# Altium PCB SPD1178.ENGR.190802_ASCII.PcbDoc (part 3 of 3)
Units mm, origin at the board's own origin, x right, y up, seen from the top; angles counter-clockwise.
Board outline 150 x 150 mm, 2 copper layers (Top Layer, Bottom Layer); 315 components, 164 nets, 838 pads, 882 vias.
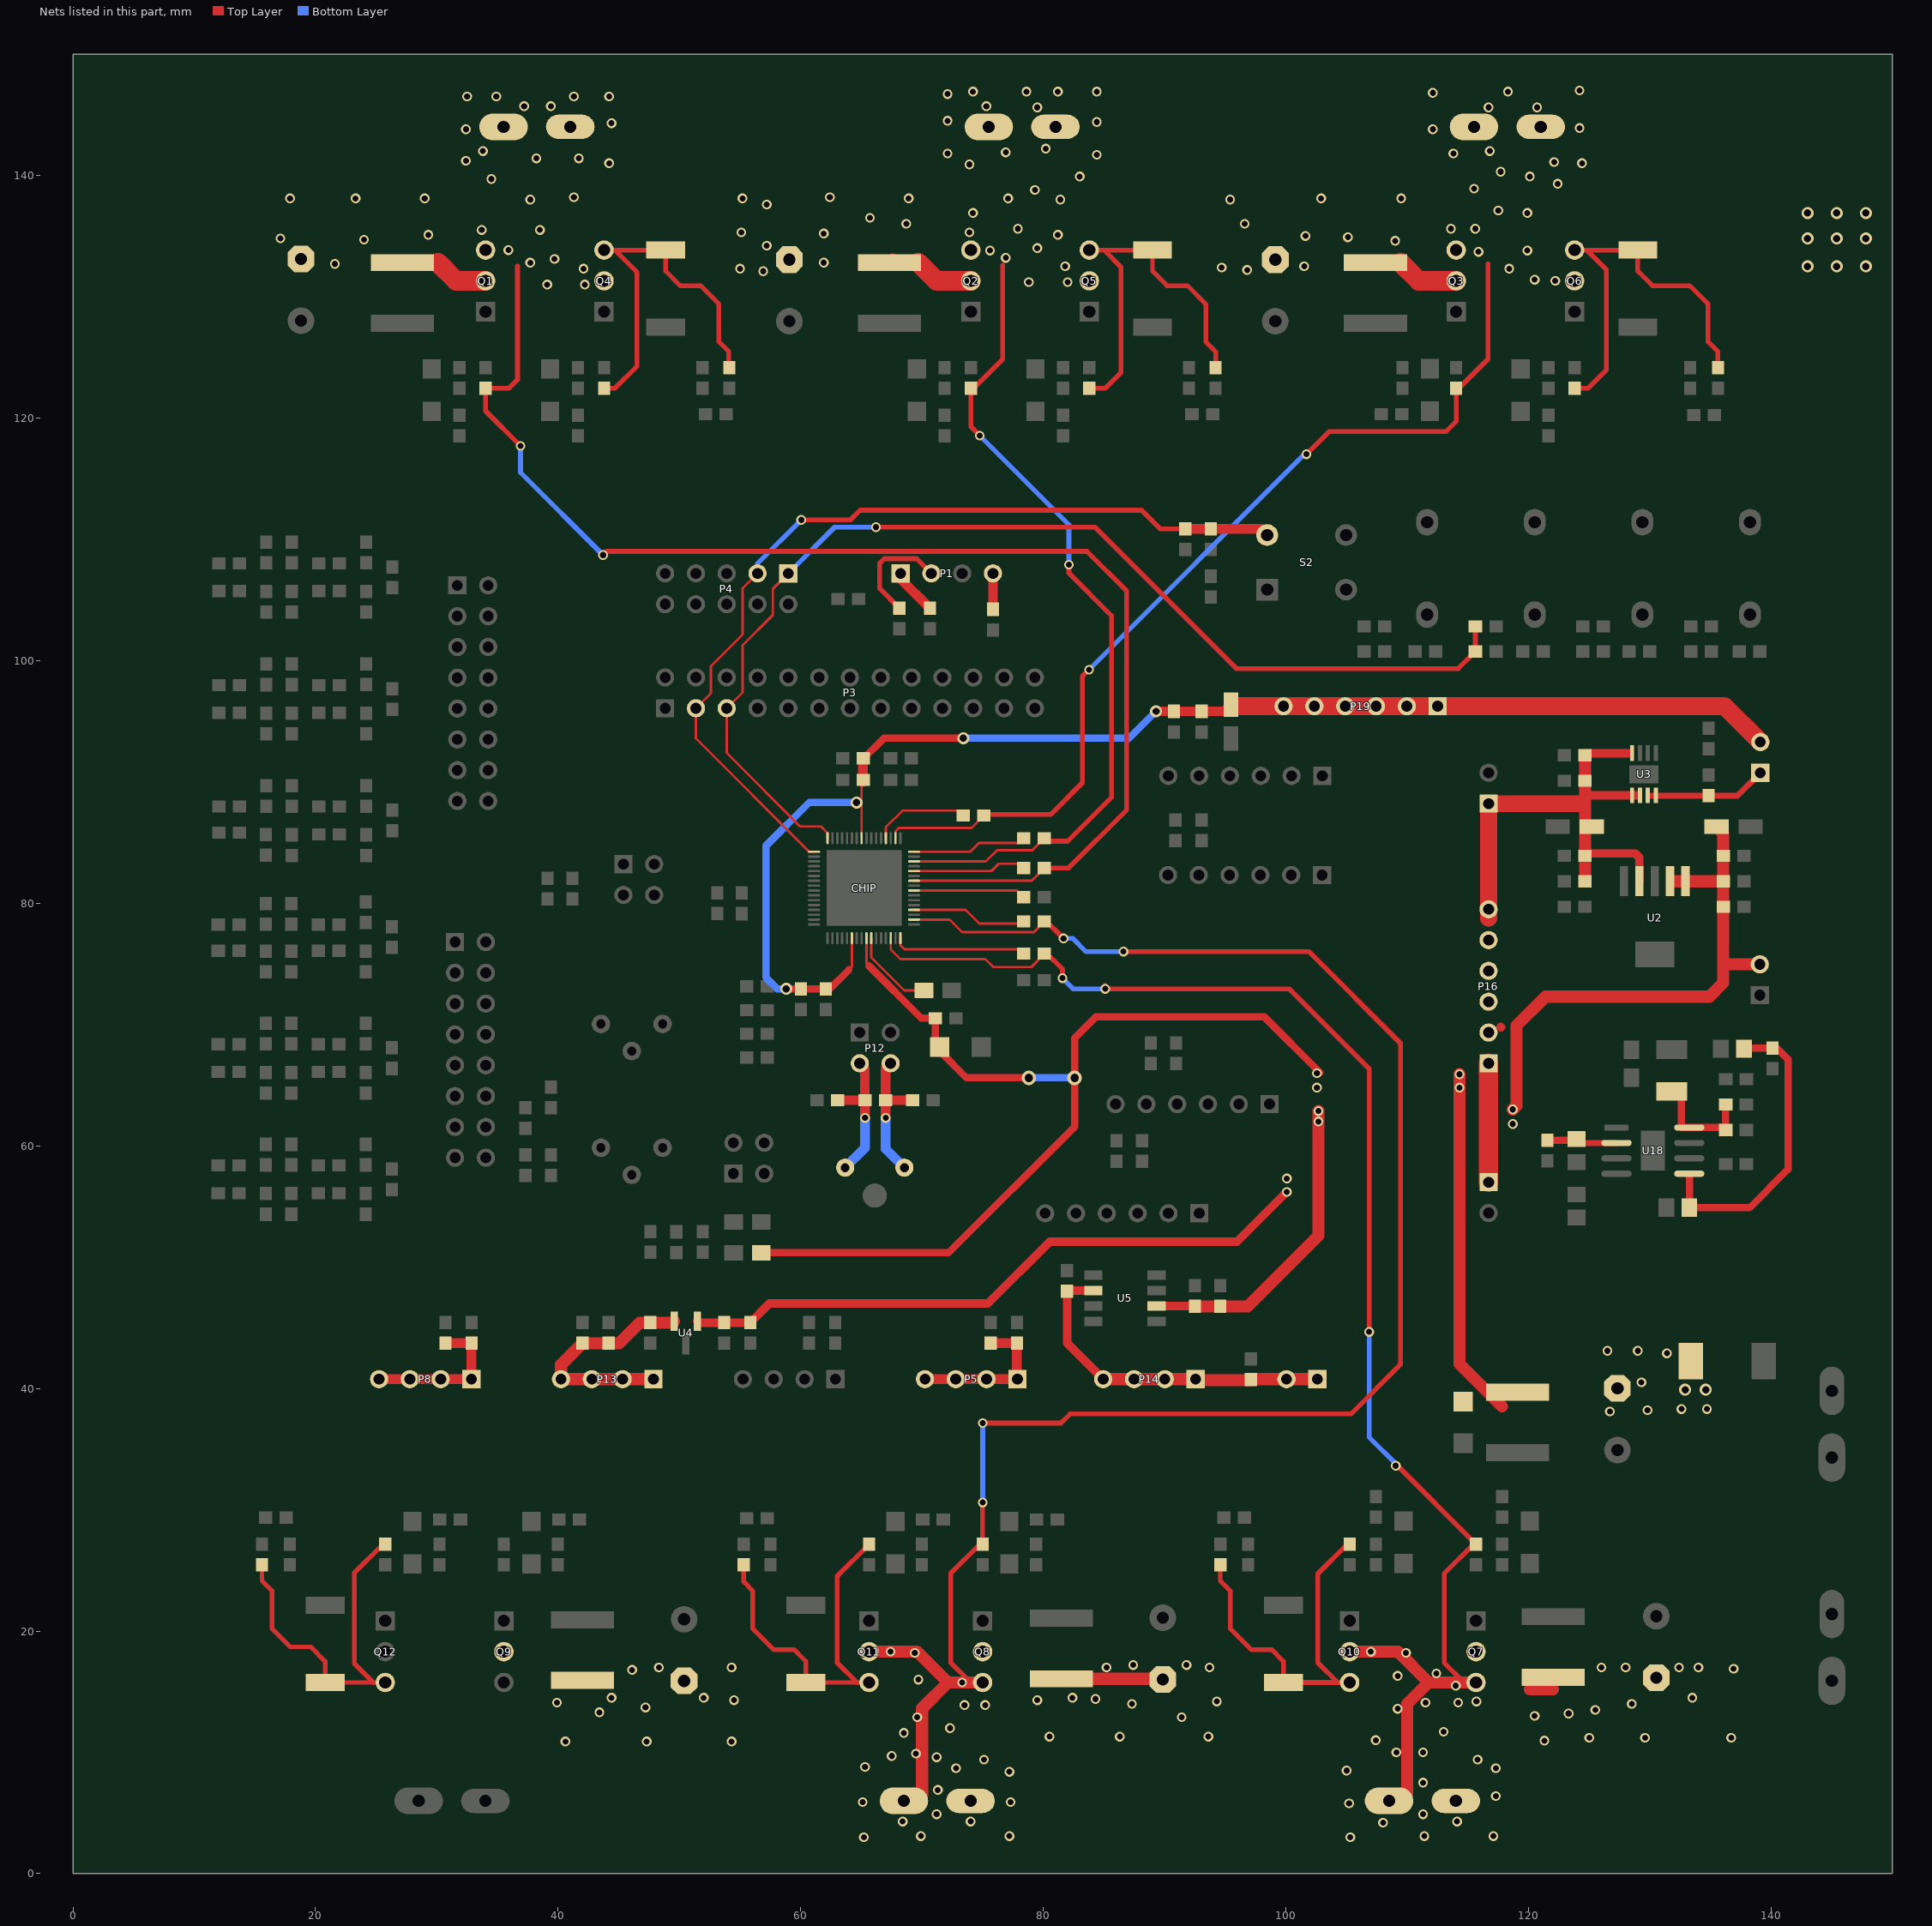
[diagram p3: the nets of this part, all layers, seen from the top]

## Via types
v1: diameter 0.8, hole 0.5, Top Layer to Bottom Layer, tented both sides, 575 vias
v2: diameter 1, hole 0.6, Top Layer to Bottom Layer, 157 vias
v3: diameter 0.8, hole 0.5, Top Layer to Bottom Layer, 69 vias
v4: diameter 1, hole 0.6, Top Layer to Bottom Layer, tented both sides, 52 vias
v5: diameter 0.8, hole 0.4, Top Layer to Bottom Layer, 16 vias
v6: diameter 1.2, hole 0.7, Top Layer to Bottom Layer, tented both sides, 7 vias
v7: diameter 0.5, hole 0.3, Top Layer to Bottom Layer, 6 vias

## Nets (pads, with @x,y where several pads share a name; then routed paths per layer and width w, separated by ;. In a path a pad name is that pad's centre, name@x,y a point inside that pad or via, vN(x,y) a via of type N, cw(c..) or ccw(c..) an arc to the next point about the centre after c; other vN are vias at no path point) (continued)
PX0_V: C14.2 C79.2 CHIP.34 Q8.3 Q11.2 V2.1 | length 151.7
  Top Layer w0.2: CHIP.34@69.333,78.647 72.283,78.647 73.31,77.62 79.22,77.62 C14.2@80.18,78.58
  Top Layer w0.4: 74.003,15.764 72.367,17.4 72.367,24.767 C79.2@74.755,27.155 ; C79.2@74.994,27.155 74.994,30.594 v1(75,30.6) ; v1(75,37.146) 81.446,37.146 82.2,37.9 105.353,37.9 109.446,41.993 109.446,68.444 101.875,76.015 v1(86.6,76.015) ; C14.2@80.18,78.58 v1(81.66,77.1)
  Top Layer w1: Q11.2@65.626,18.304 v1(67.4,18.304) 69.602,18.304 72.142,15.764 ; V2.1@70,6.5 70,13.622 72.142,15.764 ; Q8.3@74.994,15.764 74.003,15.764 v1(73.3,15.764) 72.142,15.764
  Bottom Layer w0.4: v1(75,30.6) v1(75,37.146) ; v1(81.66,77.1) 82.41,77.1 83.495,76.015 v1(86.6,76.015)
  other v1: 65.2,3 69.9,3.1 77.2,3.1 68.4,4.3 74,4.3 71.2,4.9 65.1,5.9 77.3,5.9 71.3,6.9 77.2,8.4 72.8,8.7 65.3,8.8 75.1,9.4 71.2,9.6 67.5,9.7 69.5,9.9 68.5,11.6 72.3,12 69.6,12.9 73.5,13.9 75.2,13.9 69.7,16 69.4,18.2
PX0_W: C15.2 C77.2 CHIP.30 Q7.3 Q10.2 W2.1 | length 123.7
  Top Layer w0.2: CHIP.30@67.413,77.117 67.413,76.203 68.216,75.4 75.215,75.4 75.877,74.738 79.008,74.738 C15.2@80.065,75.795
  Top Layer w0.4: C15.2@80.065,75.845 80.065,75.795 80.345,75.795 81.57,74.57 v1(81.57,73.82) ; v1(85.1,72.936) 100.274,72.936 106.855,66.355 v1(106.855,44.662) ; v1(109.05,33.63) 109.05,33.769 C77.2@115.664,27.155 115.455,27.155 113.037,24.737 113.037,17.4 114.673,15.764
  Top Layer w1: Q10.2@105.25,18.304 109.226,18.304 111.766,15.764 ; W2.1@110,6.5 110,13.998 111.766,15.764 ; Q7.3@115.664,15.764 114.673,15.764 111.766,15.764
  Bottom Layer w0.4: v1(81.57,73.82) 82.454,72.936 v1(85.1,72.936) ; v1(106.855,44.662) 106.855,35.975 109.05,33.78 v1(109.05,33.63)
  other v1: 105.3,3 111.4,3.1 117.1,3.1 108,4.2 114.1,4.3 111.3,4.9 105.2,5.8 117.3,6.4 111.3,7.5 105,8.5 117.3,8.7 115.8,9.4 109.1,10 111.3,10 107.4,11 113,11.7 109.2,13.6 111.5,14.1 114.2,14.1 115.7,14.2 114,15.5 109.2,16.3 112.4,16.5 109.9,18.2 107,18.3
PX1_U: C22.2 C75.2 CHIP.50 Q3.3 Q6.2 U1.1 | length 80.1
  Top Layer w0.2: CHIP.50@67.813,85.367 67.813,85.933 68.08,86.2 74.08,86.2 C22.2@75.1,87.22
  Top Layer w0.4: C22.2@75.1,87.22 75.2,87.32 80.61,87.32 83.22,89.93 83.22,98.71 v1(83.76,99.25) ; v3@101.493,116.98 v3@101.601,117.089 ; v3(101.68,117.01) 103.54,118.87 113.18,118.87 114.029,119.719 C75.2@114.029,122.451 114.251,122.451 116.656,124.856 116.656,132.7
  Top Layer w1: Q3.3@114.003,133.842 Q3.3@114.019,133.842
  Bottom Layer w0.4: v1(83.76,99.25) 83.763,99.25 v3@101.493,116.98
  other v1: 122.2,131.302 120.5,131.4 118.4,132.3 115.869,133.7 119.9,133.8 113.6,135.6 115.6,135.6 119.9,136.9 117.5,137.1 115.5,138.9 122.4,139.3 120.1,139.9 117.7,140.3 124.4,141 122.1,141.1 113.8,141.8 116.8,142 112.1,143.8 124.2,143.9 116.7,145.6 120.7,145.6 112.1,146.8 118.3,146.9 124.2,147
PX1_V: C23.2 C74.2 CHIP.46 Q2.3 Q5.2 V1.1 | length 68.6
  Top Layer w0.2: CHIP.46@69.333,83.447 75.257,83.447 76.18,84.37 79.08,84.37 C23.2@80.07,85.36
  Top Layer w0.4: v1(74.75,118.55) 74.024,119.276 C74.2@74.024,122.451 74.251,122.451 76.651,124.851 76.651,132.6 ; C23.2@80.07,85.36 80.32,85.11 82,85.11 85.61,88.72 85.61,103.71 82.1,107.22 v1(82.1,107.91)
  Top Layer w1: Q2.3@74.008,133.842 Q2.3@74.024,133.842
  Bottom Layer w0.4: v1(74.75,118.55) 82.1,111.2 v1(82.1,107.91)
  other v1: 78.8,131.2 82,131.2 81.8,132.5 76.9,133.2 75.6,133.8 79.5,134 81.2,135.1 73.9,135.3 77.9,135.6 74.2,136.9 81.4,138 77.1,138.1 79.3,138.8 83,139.9 73.9,140.9 84.4,141.7 72.1,141.8 76.9,141.9 80.2,142.2 84.4,144.4 72.1,144.5 79.5,145.6 75.3,145.7 72.1,146.7 74.2,146.9 78.6,146.9 81.2,146.9 84.4,146.9
PX1_W: C24.2 C71.2 CHIP.42 Q1.3 Q4.2 W1.1 | length 112.7
  Top Layer w0.2: CHIP.42@69.333,81.847 79.047,81.847 80.065,82.865 C24.2@80.065,82.9
  Top Layer w0.4: 36.646,132.5 36.646,123.156 35.941,122.451 C71.2@34.019,122.451 34.019,120.581 v1(36.9,117.7) ; v1(43.7,108.7) 44,109 83.6,109 86.87,105.73 86.87,87.69 82.08,82.9 C24.2@80.07,82.9
  Top Layer w1: Q1.3@34.013,133.842 Q1.3@34.019,133.842 Q1.3@34.029,133.842
  Bottom Layer w0.4: v1(36.9,117.7) 36.9,115.5 v1(43.7,108.7)
  other v1: 39.1,131 42.2,131 42.1,132.3 37.7,132.8 39.7,133.1 35.9,133.842 33.7,135.5 38.5,135.5 37.7,138 41.3,138.2 34.5,139.7 44.2,141 32.4,141.2 38.2,141.4 41.7,141.4 33.8,142 32.4,143.8 44.4,144.3 37.2,145.7 39.4,145.7 32.5,146.5 34.9,146.5 41.3,146.5 44.2,146.5
RU0: C82.2 Q12.3 R30.2 R185.1 | length 31
  Top Layer w0.381: R185.1@15.588,25.455 15.588,24.146 16.404,23.33 16.404,20.209 17.913,18.7 19.6,18.7 20.795,17.505 R30.2@20.795,15.764 24.757,15.764 Q12.3@25.748,15.764
  Top Layer w0.4: 24.757,15.764 23.2,17.321 23.2,24.8 25.555,27.155 C82.2@25.748,27.155
RU1: C76.2 Q6.3 R15.2 R155.1 | length 33.2
  Top Layer w0.381: Q6.3@123.792,133.842 R15.2@128.999,133.842 128.999,132.101 130.194,130.906 133.281,130.906 134.79,129.397 134.79,126.276 135.606,125.46 R155.1@135.606,124.151
  Top Layer w0.4: C76.2@123.792,122.451 124.9,122.451 126.419,123.97 126.419,132.206 124.783,133.842
RV0: C80.2 Q11.3 R29.2 R175.1 | length 31.2
  Top Layer w0.381: R175.1@55.3,25.45 55.3,24.058 56.028,23.33 56.028,20.209 57.761,18.476 59.448,18.476 60.419,17.505 R29.2@60.419,15.764 64.635,15.764 Q11.3@65.626,15.764
  Top Layer w0.4: 64.635,15.764 62.999,17.4 62.999,24.528 C80.2@65.626,27.155
RV1: C73.2 Q5.3 R14.2 R145.1 | length 31.9
  Top Layer w0.381: R14.2@88.994,133.842 88.994,132.101 90.189,130.906 91.876,130.906 93.385,129.397 93.385,126.276 94.201,125.46 R145.1@94.2,124.15
  Top Layer w0.4: C73.2@83.787,122.451 85.1,122.451 86.4,123.751 86.4,132.437 84.995,133.842 ; Q5.3@83.787,133.842 84.995,133.842 ; R14.2@88.994,133.842 84.995,133.842
RW0: C78.2 Q10.3 R28.2 R165.1 | length 31.6
  Top Layer w0.381: R165.1@94.582,25.455 94.582,24.146 95.398,23.33 95.398,20.209 97.131,18.476 98.818,18.476 99.789,17.505 R28.2@99.789,15.764
  Top Layer w0.4: R28.2@99.789,15.764 104.259,15.764 ; Q10.3@105.25,15.764 104.259,15.764 ; C78.2@105.25,27.155 105.055,27.155 102.623,24.723 102.623,17.4 104.259,15.764
RW1: C72.2 Q4.3 R13.2 R135.1 | length 31.7
  Top Layer w0.381: R13.2@48.862,133.842 48.862,132.101 50.057,130.906 51.744,130.906 53.253,129.397 53.253,126.276 54.069,125.46 R135.1@54.069,124.151
  Top Layer w0.4: C72.2@43.782,122.451 44.682,122.451 46.5,124.269 46.5,132.013 44.671,133.842 ; Q4.3@43.782,133.842 44.671,133.842 ; R13.2@48.862,133.842 44.671,133.842
TRSTN: CHIP.64 CL8.1 P3.5 P4.1 R31.1 | length 94.2
  Top Layer w0.2: P4.1@58.978,107.188 57.7,105.91 57.7,103.75 55.2,101.25 55.2,97.371 P3.5@53.898,96.069 53.898,92.382 59.95,86.33 61.67,86.33 62.213,85.787 CHIP.64@62.213,85.367
  Top Layer w0.4: v1(66.2,111) 84.251,111 95.911,99.34 114.2,99.34 R31.1@115.61,100.75 CL8.1@115.61,102.81
  Bottom Layer w0.4: P4.1@58.978,107.188 62.79,111 v1(66.2,111) v1@66.2,110.9
UART_RXD: P1.2 R64.2 | length 9.3
  Top Layer w0.4: R64.2@68.13,104.32 66.51,105.94 66.51,108.03 66.88,108.4 69.553,108.4 P1.2@70.765,107.188
UART_TXD: P1.1 R75.2 | length 3.4
  Top Layer w0.8: P1.1@68.225,106.745 R75.2@70.65,104.32
VBAT: C1.1 C2.1 C3.1 C4.1 C5.1 C6.1 C16.1 C17.1 C18.1 C19.1 C20.1 C21.1 C28.1 C29.1 C30.1 CHIP.25 CL32.2 CL33.2 F1.2 Q1.2 Q2.2 Q3.2 Q7.2 Q8.2 Q9.2 R57.1 R58.1 R440.2 U18.2 | length 155.1
  Top Layer w0.2: 65.413,75.047 CHIP.25@65.413,77.117
  Top Layer w0.5: R58.1@124.276,60.24 U18.2@127.244,60.24
  Top Layer w0.6: C18.1@50.346,15.931 C18.1@50.386,15.891 ; R440.2@56.752,51.181 72.181,51.181 82.58,61.58 82.58,68.88 84.34,70.64 98.2,70.64 v1@102.79,66.05 ; 65.62,74.84 69.94,70.52 CL33.2@71.08,70.52 71.08,68.506 CL32.2@71.446,68.14 71.446,67.814 73.66,65.6 v6(78.8,65.6) ; R57.1@121.548,60.455 123.861,60.455 R58.1@123.961,60.555 R58.1@124.276,60.24
  Top Layer w1: C21.1@40.935,15.931 C21.1@42.004,15.931 ; C20.1@79.442,16.058 C20.1@81.471,16.058 89.813,16.058 C17.1@89.853,16.018 ; v1(114.3,65.9) v1(114.3,64.8) 114.3,42.014 117.8,38.515 ; 120.115,15.185 122.014,15.185
  Top Layer w1.016: C4.1@27.17,132.807 30.093,132.807 ; C5.1@67.323,132.807 C5.1@67.815,132.807 ; C5.1@67.569,133.053 C5.1@67.815,132.807 ; C5.1@69.693,132.807 C5.1@67.815,132.807 ; C6.1@107.374,132.807 C6.1@109.443,132.807
  Top Layer w1.6: 30.093,132.807 31.598,131.302 Q1.2@34.019,131.302 ; C5.1@69.693,132.807 71.198,131.302 Q2.2@74.024,131.302 ; C6.1@109.443,132.807 110.948,131.302 Q3.2@114.029,131.302
  Bottom Layer w0.6: v6(78.8,65.6) v6(82.58,65.6)
  other v1: 40.6,10.9 47.3,10.9 54.3,10.9 121.3,10.967 125,11.2 129.6,11.2 136.7,11.2 80.5,11.3 86.3,11.3 93.6,11.3 91.4,12.9 120.5,13 123.3,13.2 43.4,13.3 125.5,13.5 47.2,13.7 87.3,14 128.5,14 39.9,14.1 94.3,14.2 54.5,14.3 79.5,14.3 84.3,14.4 44.4,14.5 52,14.5 82.4,14.5 133.5,14.5 46.1,16.8 136.9,16.9 48.3,17 54.3,17 85.2,17 93.7,17 126,17 128,17 132.4,17 134,17 87.4,17.2 91.8,17.2 126.7,38.1 129.8,38.2 132.6,38.3 134.7,38.3 129.3,40.5 131.4,42.9 126.5,43.1 129,43.1 102.55,64.8 102.55,65.99 56.9,132.1 96.8,132.2 55,132.3 94.7,132.4 101.5,132.5 21.6,132.7 61.9,132.807 57.2,134.2 109,134.6 24,134.7 17.1,134.8 105.1,134.9 101.6,135 29.3,135.1 61.9,135.2 55.1,135.3 68.7,136 96.6,136 65.7,136.5 57.2,137.6 95.4,138 17.9,138.1 23.3,138.1 29,138.1 55.2,138.1 68.9,138.1 102.9,138.1 109.5,138.1 62.4,138.2
  other v2: 132.9,39.9 134.6,39.9
  other v4: 143,132.5 145.4,132.5 147.8,132.5 143,134.8 145.4,134.8 147.8,134.8 143,136.9 145.4,136.9 147.8,136.9
VBOOT0_U: C13.1 CHIP.40 | length 9.3
  Top Layer w0.2: CHIP.40@69.333,81.047 77.823,81.047 C13.1@78.37,80.5
VBOOT0_V: C14.1 CHIP.36 | length 9.7
  Top Layer w0.2: CHIP.36@69.333,79.447 73.593,79.447 74.72,78.32 78.01,78.32 C14.1@78.37,78.68
VBOOT0_W: C15.1 CHIP.32 | length 11.1
  Top Layer w0.2: CHIP.32@68.213,77.117 68.213,76.534 68.547,76.2 78.238,76.2 78.238,75.972 C15.1@78.36,75.85
VBOOT1_U: C22.1 CHIP.52 | length 8
  Top Layer w0.2: CHIP.52@67.013,85.367 67.013,86.264 68.379,87.63 72.99,87.63 C22.1@73.4,87.22
VBOOT1_V: C23.1 CHIP.48 | length 9.5
  Top Layer w0.2: CHIP.48@69.333,84.247 73.987,84.247 74.7,84.96 77.97,84.96 C23.1@78.37,85.36
VBOOT1_W: C24.1 CHIP.44 | length 9.4
  Top Layer w0.2: CHIP.44@69.333,82.647 75.727,82.647 76.33,83.25 78.02,83.25 C24.1@78.37,82.9
VCAP12: CB3.1 CHIP.22 CHIP.57 CL11.2 CL12.2 CL25.1 CL26.1 CL30.2 CL31.2 P18.2 P19.1 P19.2 P19.3 P19.4 P19.5 P19.6 | length 113.8
  Top Layer w0.2: 63.97,74.51 64.213,74.753 CHIP.22@64.213,77.117 ; CHIP.57@65.013,85.367 CL31.2@65.013,90
  Top Layer w0.6: v2(58.81,72.94) CL12.2@60.02,72.94 62.4,72.94 63.97,74.51 ; CL30.2@65.15,91.9 66.85,93.6 v2(73.4,93.6)
  Top Layer w0.8: CL31.2@65.11,90 CL30.2@65.11,92.02 ; v2(89.29,95.818) CL25.1@90.756,95.818 CL26.1@93.042,95.818 94.905,95.818 CB3.1@95.455,96.368
  Top Layer w1.5: CB3.1@95.75,96.24 136.155,96.24 P18.2@139.105,93.29
  Bottom Layer w0.6: v2(58.81,72.94) 58.06,72.94 57.13,73.87 57.13,84.74 60.69,88.3 v2(64.6,88.3) ; v2(73.4,93.6) 87.032,93.6 87.052,93.58 v2(89.29,95.818)
VCC: P1.4 R62.1 | length 3
  Top Layer w0.8: R62.1@75.845,104.228 P1.4@75.845,107.188
VDAC_BUF0: CL4.1 P5.1 P5.2 P5.3 P5.4 R169.1 | length 12.8
  Top Layer w0.8: P5.4@70.237,40.767 P5.3@72.777,40.767 P5.2@75.317,40.767 P5.1@77.857,40.767 77.818,40.806 CL4.1@77.818,43.727 R169.1@75.659,43.727
VDAC_BUF1: CL5.1 P8.1 P8.2 P8.3 P8.4 R168.1 | length 12.7
  Top Layer w0.8: P8.4@25.237,40.767 P8.3@27.777,40.767 P8.2@30.317,40.767 P8.1@32.857,40.767 32.86,40.77 R168.1@32.86,43.727 CL5.1@30.701,43.727
VDD_1V3: CL24.1 P18.1 U3.3 U3.4 | length 10
  Top Layer w0.5: U3.3@129.92,88.86 CL24.1@134.85,88.86 137.215,88.86 P18.1@139.105,90.75
VDD_3V3: CB1.1 CB6.1 CB8.2 CF2.1 CL22.1 CL23.1 CL29.2 P16.1 P16.2 P16.3 P16.4 P16.5 P16.6 P27.1 P28.1 U2.4 U3.1 U3.2 U3.8 U4.1 | length 105.8
  Top Layer w0.7: U4.1@51.473,45.537 51.583,45.427 CL29.2@53.688,45.427 CB8.2@55.847,45.427 57.42,47 75.43,47 80.53,52.1 95.97,52.1 v1(100.07,56.2) ; 117.7,69.8 117.724,69.776 ; CL22.1@124.65,83.9 124.85,84.1 128.8,84.1 129.13,83.77 U2.4@129.13,81.825 ; CB1.1@124.65,85.75 CB1.1@125.2,86.3 ; CB6.1@124.65,92.2 124.81,92.36 128.35,92.36 ; 124.68,88.89 U3.1@128.53,88.89 129,88.89
  Top Layer w1: CL23.1@124.65,81.8 CL22.1@124.65,83.9 124.65,85.75 CF2.1@124.65,90.1 CB6.1@124.65,92.2
  Top Layer w1.4: P16.6@116.7,78.76 P16.6@116.7,79.5 116.7,87.96 116.94,88.2 124.35,88.2
  Top Layer w1.6: P27.1@116.7,57 P16.1@116.7,66.8
  other v1: 100.07,57.3
VDD_5V: CB2.1 CB5.1 CB10.2 CF1.1 CL21.1 CL38.2 P17.2 U2.1 U2.2 U5.2 | length 72.8
  Top Layer w0.7: U5.2@89.33,46.8 CB10.2@92.506,46.8
  Top Layer w1: CB10.2@92.506,46.764 CL38.2@94.586,46.764 ; 93.486,46.764 96.844,46.764 102.67,52.59 v1(102.67,62.87) ; v1(118.7,63) 119,63.3 119,69.9 121.4,72.3 134.9,72.3 136.05,73.45 136.05,74.961 ; U2.2@131.98,81.825 132.005,81.8 CF1.1@136.05,81.8 ; CB2.1@135.5,86.3 136.05,85.75 CL21.1@136.05,83.9 CF1.1@136.05,81.8 ; P17.2@139.06,74.961 136.05,74.961 ; 136.05,74.961 CB5.1@136.05,79.7 CF1.1@136.05,81.8
  other v1: 118.7,61.8 102.67,62
VDDG: CHIP.26 CL621.2 | length 7
  Top Layer w0.2: CHIP.26@65.813,77.117 65.813,75.54 68.533,72.82 CL621.2@70.157,72.82
VFB: C56.2 R53.2 R54.1 U18.5 | length 24.9
  Top Layer w0.6: U18.5@133.25,57.51 R54.1@133.25,54.9 138.22,54.9 141.38,58.06 141.38,67.14 140.47,68.05 C56.2@140.1,68.05 138.1,68.05 R53.2@138.05,68
VREF_1V2: CB9.2 CL13.2 P13.1 P13.2 P13.3 P13.4 R36.1 U4.2 | length 19.6
  Top Layer w1: P13.1@47.857,40.767 P13.2@45.317,40.767 P13.3@42.777,40.767 P13.4@40.237,40.767 40.237,41.96 CL13.2@42.004,43.727 R36.1@44.163,43.727 45.027,43.727 46.727,45.427 CB9.2@47.592,45.427 49.443,45.427 U4.2@49.553,45.537
VREF_3V3: CL14.2 CL39.2 P14.1 P14.2 P14.3 P14.4 P117.1 P117.2 U5.6 | length 28.3
  Top Layer w0.7: CL39.2@81.95,48 81.95,43.747 P14.4@84.93,40.767 ; CL39.2@82.02,48.07 U5.6@84.123,48.07
  Top Layer w1.016: P14.4@84.93,40.767 P14.3@87.47,40.767 P14.2@90.01,40.767 P14.1@92.55,40.767 92.638,40.679 97.122,40.679 97.21,40.767 P117.2@100.043,40.767 P117.1@102.583,40.767
VSW: C59.2 L1.1 R52.2 U18.8 | length 8.6
  Top Layer w0.6: L1.1@132.6,64.5 132.6,61.566 132.544,61.51 U18.8@133.244,61.51 C59.2@135.74,61.51 ; C59.2@136.04,61.51 C59.2@136.25,61.3 R52.2@136.25,63.4
XIN: CL18.2 P12.3 R35.1 Y1.1 | length 11.7
  Top Layer w0.8: CL18.2@63.047,63.754 R35.1@65.284,63.754 ; P12.3@64.864,66.802 65.284,66.382 R35.1@65.284,63.754 ; v1(65.3,62.3) 65.3,63.738 R35.1@65.284,63.754
  Bottom Layer w0.8: Y1.1@63.66,58.2 65.3,59.84 v1(65.3,62.3)
XIO: CL19.2 P12.4 R35.2 Y1.2 | length 11.7
  Top Layer w0.8: v1(67,62.3) 67,63.738 R35.2@66.984,63.754 ; P12.4@67.404,66.802 66.984,66.382 R35.2@66.984,63.754 ; CL19.2@69.221,63.754 R35.2@66.984,63.754
  Bottom Layer w0.8: v1(67,62.3) 67,59.74 Y1.2@68.54,58.2
XRSTN: CHIP.1 CL3.2 P3.3 P4.3 R63.1 S2.2 | length 74.8
  Top Layer w0.2: P4.3@56.438,107.188 55.2,105.95 55.2,102.141 52.6,99.541 52.6,97.311 P3.3@51.358,96.069 51.358,93.582 60.693,84.247 CHIP.1@61.094,84.247
  Top Layer w0.4: v1(60.038,111.6) 64.1,111.6 64.9,112.4 88.1,112.4 89.65,110.85 R63.1@91.7,110.85 ; S2.2@97.95,110.85 S2.2@98.45,110.35
  Top Layer w0.8: R63.1@91.7,110.85 CL3.2@93.8,110.85 S2.2@97.95,110.85
  Bottom Layer w0.4: P4.3@56.438,107.188 56.438,108 v1(60.038,111.6)
pads on no net: P3.19 P4.5 P7.13 P7.15 P9.13 P9.15 S2.3 S2.4 U3.7 U5.1 U5.3 U5.5 U5.7 U5.8

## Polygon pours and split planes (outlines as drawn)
AGND on Bottom Layer "Bottom Layer-No Net" (hatched 90Degree grid 0.2 track 0.2, remove dead copper, pour order 150): 17 vertices, not listed, extent 92.416,30.7 98.9,31.567
AGND on Bottom Layer "Bottom Layer-No Net" (hatched 90Degree grid 0.2 track 0.2, remove dead copper, pour order 149): 17 vertices, not listed, extent 52.8,30.9 59.816,31.9
GND on Bottom Layer "Bottom Layer-No Net" (solid, remove dead copper, pour order 90): 90 vertices, not listed, extent 16.6,18.9 148.7,130.3
VBAT on Bottom Layer "Bottom Layer-No Net" (solid, remove dead copper, pour order 85): 49 vertices, not listed, extent 39.3,10.3 139.7,43.7
AGND on Bottom Layer "Bottom Layer-No Net" (solid, remove dead copper, pour order 86): 32 vertices, not listed, extent 13.1,39.3 100.498,112.1
VBAT on Bottom Layer "Bottom Layer-No Net" (solid, remove dead copper, pour order 115): 57 vertices, not listed, extent 16.6,121.6 148.7,138.9
VBAT on Bottom Layer "Bottom Layer-No Net 1" (hatched 90Degree grid 0.2 track 0.2, remove dead copper, pour order 133): 17 vertices, not listed, extent 29.416,129.7 34,138.8
VBAT on Bottom Layer "Bottom Layer-No Net 1" (hatched 90Degree grid 0.2 track 0.2, remove dead copper, pour order 132): 17 vertices, not listed, extent 69.016,129.7 74.005,138.8
VBAT on Bottom Layer "Bottom Layer-No Net 1" (hatched 90Degree grid 0.2 track 0.2, remove dead copper, pour order 131): 18 vertices, not listed, extent 109.216,129.8 114.029,138.8
VBAT on Bottom Layer "Bottom Layer-No Net 1" (hatched 90Degree grid 0.2 track 0.2, remove dead copper, pour order 130): 115.683,18.967 117.067,18.967 120.2,22.1 120.2,19.2 120.2,11.416 121.216,10.4 119.616,10.4 118.889,10.4 117.722,11.567 117.683,11.606 117.683,12.367 117.683,16.306 116.622,17.367 116.389,17.6 115.5,17.6
VBAT on Bottom Layer "Bottom Layer-No Net 1" (hatched 90Degree grid 0.2 track 0.2, remove dead copper, pour order 129): 17 vertices, not listed, extent 75.019,10.4 80.6,21.3
VBAT on Bottom Layer "Bottom Layer-No Net 1" (hatched 90Degree grid 0.2 track 0.2, remove dead copper, pour order 127): 35.519,17.702 35.519,17.602 36.219,17.602 36.919,16.902 37.519,16.302 37.519,13.902 37.519,11.602 38.119,11.002 38.721,10.4 40.743,10.4 40.306,17.8 39.452,17.8 38.25,19.002 35.519,19.002
AGND on Bottom Layer "Bottom Layer-No Net 1" (hatched 90Degree grid 0.2 track 0.2, remove dead copper, pour order 80): 26 vertices, not listed, extent 2.1,33.9 99.545,116.888
GND on Bottom Layer "Bottom Layer-No Net 1" (hatched 90Degree grid 0.2 track 0.2, remove dead copper, pour order 81): 22.5,32.2 28.9,38.6 36.2,38.6 103.58,38.6 104.83,39.85 104.83,51.06 106.97,53.2 114.5,53.2 114.5,34.8 112.4,32.7 110.3,30.6 108.4,30.6 24.1,30.6
AGND on Bottom Layer "Bottom Layer-No Net 1" (hatched 90Degree grid 0.2 track 0.2, remove dead copper, pour order 125): 48.6,116.967 55.1,116.967 55.7,117.567 56.016,117.883 56.016,118.284 55.533,118.767 55.1,119.2 49.9,119.2 49.8,119.2 48.6,118 48.416,117.816 48.416,117.3 48.416,117.152 48.6,116.967
AGND on Bottom Layer "Bottom Layer-No Net 1" (hatched 90Degree grid 0.2 track 0.2, remove dead copper, pour order 138): 125.73,116.07 127.4,114.4 128.4,113.4 131.633,113.4 132.6,114.367 132.9,114.667 132.9,115.367 132.9,115.5 132.633,115.767 132.6,115.8 129.9,115.8 129,116.7 128.51,117.19 126.015,117.19 125.73,116.905
AGND on Bottom Layer "Bottom Layer-No Net 1" (hatched 90Degree grid 0.2 track 0.2, remove dead copper, pour order 141): 18 vertices, not listed, extent 86.416,114.367 93.35,117.3
AGND on Bottom Layer "Bottom Layer-No Net 1" (hatched 90Degree grid 0.2 track 0.2, remove dead copper, pour order 95): 21 vertices, not listed, extent 43.03,48.04 55.2,89.11
GND on Bottom Layer "Bottom Layer-No Net 1" (hatched 90Degree grid 0.2 track 0.2, remove dead copper, pour order 101): 22 vertices, not listed, extent 54,69.51 59.45,90.15
AGND on Top Layer "Bottom Layer-No Net 1" (hatched 90Degree grid 0.2 track 0.2, remove dead copper, pour order 158): 27 vertices, not listed, extent 80.28,46.54 94.51,51.45
AGND on Top Layer "Bottom Layer-No Net 1" (hatched 90Degree grid 0.2 track 0.2, remove dead copper, pour order 157): 31 vertices, not listed, extent 81.79,57.1 99.81,67.2
GND on Top Layer "Bottom Layer-No Net 1" (hatched 90Degree grid 0.2 track 0.2, remove dead copper, pour order 156): 51.27,98.08 51.19,98 48.79,98 48.68,98 48.25,98.43 48.21,98.47 48.21,100.01 48.21,101.29 48.49,101.57 49.43,101.57 49.77,101.57 50.93,100.41 51.85,99.49 51.85,98.53
GND on Top Layer "Bottom Layer-No Net 1" (hatched 90Degree grid 0.2 track 0.2, remove dead copper, pour order 154): 66.62,98.06 66.61,98.05 62.96,98.05 56.49,98.05 56.04,98.5 56.04,99 57.04,100 58.17,101.13 61.02,101.13 64.74,101.13 66.77,99.1
GND on Top Layer "Bottom Layer-No Net 1" (hatched 90Degree grid 0.2 track 0.2, remove dead copper, pour order 152): 72.1,100.54 72.1,106.93 72.89,107.72 73.08,107.91 73.61,107.91 73.67,107.91 74.17,107.41 74.58,107 74.58,105.45 74.58,104.61 73.33,103.36 73.16,103.19 73.16,101.86 74,101.02
GND on Top Layer "Bottom Layer-No Net 1" (hatched 90Degree grid 0.2 track 0.2, remove dead copper, pour order 151): 71.58,98.05 79.3,98.05 79.8,98.55 79.8,98.96 77.53,101.23 72.47,101.23 71.58,100.34 71.14,99.9 71.14,98.5
AGND on Top Layer "Bottom Layer-No Net" (hatched 90Degree grid 0.2 track 0.2, remove dead copper, pour order 148): 55,31.2 55,31.8 54.6,32.2 23.5,32.2 19.2,36.5 18.7,36.5 18.216,36.5 17.616,35.9 17.416,35.7 17.416,35.2 17.416,31.784 18.4,30.8 32.4,30.8 54.7,30.8 55,31.1
AGND on Top Layer "Bottom Layer-No Net" (hatched 90Degree grid 0.2 track 0.2, remove dead copper, pour order 147): 94.5,31 94.5,31.8 94.3,32 93.9,32.4 93.5,32.4 58.8,32.4 58.3,31.9 58.3,31.1 58.3,30.8 58.7,30.4 63.9,30.4 94,30.4 94.4,30.8 94.5,30.9 94.5,31
AGND on Top Layer "Bottom Layer-No Net" (hatched 90Degree grid 0.2 track 0.2, remove dead copper, pour order 146): 22 vertices, not listed, extent 22.7,30.65 99,40.767
AGND on Top Layer "Bottom Layer-No Net" (hatched 90Degree grid 0.2 track 0.2, remove dead copper, pour order 145): 9.016,33.9 9.016,29.684 10,28.7 11.3,28.7 13.9,28.7 14.4,29.2 14.6,29.4 14.6,30 14.6,33.684 15.6,34.684 15.317,34.967 11.3,34.967 10.067,34.967 9,33.9
VBAT on Top Layer "Bottom Layer-No Net" (solid, remove dead copper, pour order 114): 17 vertices, not listed, extent 123.5,43.3 148.7,137.8
GND on Top Layer "Bottom Layer-No Net 1" (hatched 90Degree grid 0.2 track 0.2, remove dead copper, pour order 135): 22.257,21.506 22.557,21.806 22.557,23.643 21.9,24.3 18.951,24.3 17.857,23.206 17.857,21.806 17.857,20.906 18.157,20.606 18.657,20.606 19.057,20.606 19.957,21.506 21.957,21.506
GND on Top Layer "Bottom Layer-No Net 1" (hatched 90Degree grid 0.2 track 0.2, remove dead copper, pour order 136): 61.881,21.506 62.181,21.806 62.181,23.006 61.981,23.206 61.481,23.706 59.081,23.706 57.981,23.706 57.481,23.206 57.481,21.806 57.481,20.906 57.781,20.606 58.281,20.606 58.681,20.606 59.581,21.506 61.581,21.506
GND on Top Layer "Bottom Layer-No Net 1" (hatched 90Degree grid 0.2 track 0.2, remove dead copper, pour order 137): 101.251,21.506 101.551,21.806 101.551,23.006 101.351,23.206 100.851,23.706 98.451,23.706 97.351,23.706 96.851,23.206 96.851,21.806 96.851,20.906 97.151,20.606 97.651,20.606 98.051,20.606 98.951,21.506 100.951,21.506
GND on Top Layer "Bottom Layer-No Net 1" (hatched 90Degree grid 0.2 track 0.2, remove dead copper, pour order 139): 127.537,128.1 127.237,127.8 127.237,126.6 127.437,126.4 127.937,125.9 130.337,125.9 132.61,125.9 133.16,126.45 133.16,128.61 132.77,129 131.137,129 130.737,129 129.837,128.1 127.837,128.1
GND on Top Layer "Bottom Layer-No Net 1" (hatched 90Degree grid 0.2 track 0.2, remove dead copper, pour order 140): 87.532,128.1 87.232,127.8 87.232,126.6 87.432,126.4 87.932,125.9 90.332,125.9 91.432,125.9 91.932,126.4 91.932,127.8 91.932,128.7 91.632,129 91.132,129 90.732,129 89.832,128.1 87.832,128.1
GND on Top Layer "Bottom Layer-No Net 1" (hatched 90Degree grid 0.2 track 0.2, remove dead copper, pour order 142): 47.4,128.1 47.1,127.8 47.1,126.6 47.3,126.4 47.8,125.9 50.2,125.9 51.3,125.9 51.8,126.4 51.8,127.8 51.8,128.7 51.5,129 51,129 50.6,129 49.7,128.1 47.7,128.1
VBAT on Top Layer "Bottom Layer-No Net 1" (hatched 90Degree grid 0.2 track 0.2, remove dead copper, pour order 119): 115.683,17.706 115.683,17.606 116.383,17.606 117.083,16.906 117.683,16.306 117.683,13.906 117.683,11.606 118.283,11.006 118.889,10.4 122.1,10.4 122.1,15.289 118.683,18.706 118.383,19.006 115.683,19.006
VBAT on Top Layer "Bottom Layer-No Net 1" (hatched 90Degree grid 0.2 track 0.2, remove dead copper, pour order 120): 75.019,17.702 75.019,17.602 75.719,17.602 76.419,16.902 77.019,16.302 77.019,13.902 77.019,11.602 77.619,11.002 78.221,10.4 80.6,10.4 80.6,16.121 78.019,18.702 77.719,19.002 75.019,19.002
VBAT on Top Layer "Bottom Layer-No Net 1" (hatched 90Degree grid 0.2 track 0.2, remove dead copper, pour order 121): 35.546,17.706 35.546,17.606 36.246,17.606 36.946,16.906 37.546,16.306 37.546,13.906 37.546,11.606 38.146,11.006 38.752,10.4 40.746,10.4 40.746,16.506 38.546,18.706 38.246,19.006 35.546,19.006
VBAT on Top Layer "Bottom Layer-No Net 1" (hatched 90Degree grid 0.2 track 0.2, remove dead copper, pour order 123): 114.01,131.9 114.01,132 113.31,132 112.61,132.7 112.01,133.3 112.01,135.7 112.01,138 111.41,138.6 111.21,138.8 108.81,138.8 108.81,133.1 111.01,130.9 111.31,130.6 114.01,130.6
VBAT on Top Layer "Bottom Layer-No Net 1" (hatched 90Degree grid 0.2 track 0.2, remove dead copper, pour order 124): 74.005,131.9 74.005,132 73.305,132 72.605,132.7 72.005,133.3 72.005,135.7 72.005,138 71.405,138.6 71.205,138.8 68.805,138.8 68.805,133.1 71.005,130.9 71.305,130.6 74.005,130.6
VBAT on Top Layer "Bottom Layer-No Net 1" (hatched 90Degree grid 0.2 track 0.2, remove dead copper, pour order 126): 34,131.9 34,132 33.3,132 32.6,132.7 32,133.3 32,135.7 32,138 31.4,138.6 31.2,138.8 28.8,138.8 28.8,133.1 31,130.9 31.3,130.6 34,130.6
GND on Top Layer "OSC" (solid, remove dead copper, pour order 89): 61.4,54.8 71.41,54.8 73.15,56.54 73.15,63.11 69.818,66.442 69.818,69.382 66.9,72.3 64.4,72.3 63.7,71.6 63.09,70.99 63.09,68.79 60.6,66.3 59.2,64.9 59.2,57 60.5,55.7
VBAT on Top Layer "Bottom Layer-No Net" (solid, remove dead copper, pour order 94): 94.9,138.9 93.9,137.9 93.9,132.3 94.9,131.3 110.8,131.3 110.9,131.4 110.3,132 110.3,138 109.4,138.9
VBAT on Top Layer "Bottom Layer-No Net" (solid, remove dead copper, pour order 99): 60.6,138.9 55,138.9 53.9,137.8 53.9,132.4 55,131.3 70.5,131.3 70.7,131.5 70.3,131.9 70.3,132.8 70.3,137.8 69.7,138.4 69.2,138.9 67.3,138.9
VBAT on Top Layer "Bottom Layer-No Net" (solid, remove dead copper, pour order 100): 18 vertices, not listed, extent 16.6,131.3 30.898,138.9
GND on Top Layer "Bottom Layer-No Net" (solid, remove dead copper, pour order 103): 18 vertices, not listed, extent 16.6,117.9 30.6,130.3
GND on Top Layer "Bottom Layer-No Net" (solid, remove dead copper, pour order 109): 61,130.3 69.6,130.3 70.3,129.6 70.3,127.3 69.6,126.6 66.6,126.6 65.6,125.6 65.6,119.5 64.39,118.29 57.51,118.29 56.3,119.5 56.3,129.2 57.4,130.3
GND on Top Layer "Bottom Layer-No Net" (solid, remove dead copper, pour order 107): 45.505,24.992 45.505,28.691 46.163,29.348 52.637,29.348 53.205,28.781 53.205,19.792 52.313,18.9 40.1,18.9 39.3,19.7 39.3,21.787 39.854,22.341 42.854,22.341
GND on Top Layer "Bottom Layer-No Net" (solid, remove dead copper, pour order 106): 84.972,25.119 84.972,28.858 85.663,29.548 91.737,29.548 92.672,28.614 92.672,19.919 91.78,19.027 79.567,19.027 78.767,19.827 78.767,21.914 79.321,22.468 82.321,22.468
GND on Top Layer "Bottom Layer-No Net" (solid, remove dead copper, pour order 104): 109.651,130.3 110.3,129.651 110.3,127.249 109.651,126.6 106.651,126.6 104,123.949 104,122.64 101.36,120 97,120 96.3,120.7 96.3,129.149 97.451,130.3
AGND on Top Layer "Bottom Layer-No Net" (solid, remove dead copper, pour order 111): 87 vertices, not listed, extent 22.6,38.9 104.4,47.4
GND on Top Layer "Bottom Layer-No Net" (solid, remove dead copper, pour order 117): 34 vertices, not listed, extent 88.5,81.03 124.34,94.552
GND on Top Layer "Bottom Layer-No Net" (solid, remove dead copper, pour order 118): 64 vertices, not listed, extent 118.5,52.6 141.2,87.92
AGND on Top Layer "Bottom Layer-No Net 1" (hatched 90Degree grid 0.2 track 0.2, remove dead copper, pour order 82): 21 vertices, not listed, extent 2.1,33.9 15.9,116.062
AGND on Top Layer "Bottom Layer-No Net 1" (hatched 90Degree grid 0.2 track 0.2, remove dead copper, pour order 83): 18 vertices, not listed, extent 17.3,50.85 50.1,56.3
AGND on Top Layer "Bottom Layer-No Net 1" (hatched 90Degree grid 0.2 track 0.2, remove dead copper, pour order 84): 39.4,64.85 39,65.25 39,65.3 39,69.8 39.5,70.3 40.4,71.2 42.8,71.2 44.4,71.2 44.8,70.8 44.8,69.7 44.8,68.7 43.6,67.5 40.6,64.5 39.3,64.5
AGND on Top Layer "Bottom Layer-No Net 1" (hatched 90Degree grid 0.2 track 0.2, remove dead copper, pour order 87): 18.004,60.122 18.426,59.7 19.216,59.7 26.9,59.7 27.6,60.4 27.9,60.7 27.9,62.3 27.9,63.4 26.9,64.4 26.6,64.7 23.2,64.7 18.216,64.7 18.016,64.5
AGND on Top Layer "Bottom Layer-No Net 1" (hatched 90Degree grid 0.2 track 0.2, remove dead copper, pour order 93): 18.004,70.109 18.413,69.7 18.816,69.7 27,69.7 28.7,71.4 29.3,72 29.3,73.6 29.3,73.7 28.4,74.6 23.4,74.6 18.333,74.6 17.9,74.167
AGND on Top Layer "Bottom Layer-No Net 1" (hatched 90Degree grid 0.2 track 0.2, remove dead copper, pour order 98): 18.004,79.977 18.414,79.567 20.7,79.567 30.067,79.567 30.3,79.8 30.3,80.2 30.3,80.4 30,80.7 27.7,80.7 18.2,80.7 17.7,80.2
AGND on Top Layer "Bottom Layer-No Net 1" (hatched 90Degree grid 0.2 track 0.2, remove dead copper, pour order 102): 18.042,83.937 18.979,83 19.416,83 32.2,83 32.5,83.3 32.6,83.4 32.6,83.8 32.6,83.9 32.3,84.2 32.2,84.3 23.2,84.3 18.405,84.3 18.042,83.937
AGND on Top Layer "Bottom Layer-No Net 1" (hatched 90Degree grid 0.2 track 0.2, remove dead copper, pour order 105): 18.042,89.701 18.443,89.3 19.016,89.3 27.6,89.3 28.1,89.8 28.1,90.7 28.1,93.6 27.6,94.1 27.4,94.3 23.7,94.3 18.391,94.3 18.042,93.951
AGND on Top Layer "Bottom Layer-No Net 1" (hatched 90Degree grid 0.2 track 0.2, remove dead copper, pour order 108): 18.042,99.71 18.452,99.3 18.816,99.3 27.7,99.3 28.6,100.2 29.6,101.2 29.6,102.4 29.6,103.6 29.4,103.8 28.884,104.316 23.616,104.316 18.131,104.316 17.816,104
AGND on Top Layer "Bottom Layer-No Net 1" (hatched 90Degree grid 0.2 track 0.2, remove dead copper, pour order 112): 29.016,80.7 42.7,80.7 43.95,79.45 56.69,79.45 57.12,79.88 59.167,79.88 59.2,79.847 58.447,79.847 57.8,79.2 57.16,78.56 28.056,78.56 26.616,80 27.316,80.7
AGND on Top Layer "Bottom Layer-No Net 1" (hatched 90Degree grid 0.2 track 0.2, remove dead copper, pour order 113): 40.5,59.4 43.3,62.2 44.5,62.2 45.9,62.2 46.4,61.7 46.4,60.1 46.1,59.8 45.1,58.8 42.3,58.8 39.85,58.8 39.4,59.25 39.55,59.4 40.5,59.4
AGND on Top Layer "Bottom Layer-No Net 1" (hatched 90Degree grid 0.2 track 0.2, remove dead copper, pour order 116): 4.846,115.55 6.184,116.888 24.284,116.888 46.784,116.888 49.063,119.167 50.7,119.167 50.9,118.967 50.9,118.204 49.884,117.188 48.684,115.988 47.584,115.988 10.7,115.988 8.767,114.055
AGND on Top Layer "Bottom Layer-No Net 1" (hatched 90Degree grid 0.2 track 0.2, remove dead copper, pour order 122): 88.8,117.3 89.25,116.85 89.25,116.3 88.953,116 53.953,116 53.153,116 52.853,116.3 52.853,117 54.253,118.4 55.353,118.4 56.453,117.3 86.3,117.3
AGND on Top Layer "Bottom Layer-No Net 1" (hatched 90Degree grid 0.2 track 0.2, remove dead copper, pour order 128): 31 vertices, not listed, extent 17.7,109.367 132.47,115.95
AGND on Top Layer "Bottom Layer-No Net 1" (hatched 90Degree grid 0.2 track 0.2, remove dead copper, pour order 134): 91.084,113.85 102.67,113.85 104.76,115.94 128,115.94 128.416,116.356 128.416,116.767 127.993,117.19 103.531,117.191 102.09,115.75 91.184,115.75 90.384,114.95 90.384,114.55
GND on Top Layer "Bottom Layer-No Net 1" (hatched 90Degree grid 0.2 track 0.2, remove dead copper, pour order 144): 93.8,109.15 93.8,106.7 93.9,106.6 94.9,106.6 96,106.6 96.1,106.7 96.8,107.4 96.8,107.6 96.8,108.8 96.5,109.1
GND on Top Layer "Bottom Layer-No Net 1" (hatched 90Degree grid 0.2 track 0.2, remove dead copper, pour order 88): 29.1,127.1 28.7,127.1 27.3,125.7 27.1,125.5 27.1,122.7 27.1,119.1 26.7,118.7 26,118 23.2,118 23.2,125 25.3,127.1
GND on Top Layer "Bottom Layer-No Net 1" (hatched 90Degree grid 0.2 track 0.2, remove dead copper, pour order 96): 93.416,109.2 93.416,109.016 92.6,108.2 92.3,107.9 91.5,107.9 87.6,111.8 86.7,111.8 86.3,111.4 86.3,110.8 91.3,105.8 92.6,105.8 93.6,106.8 93.8,107 93.8,109.15
AGND on Top Layer "Bottom Layer-No Net 1" (hatched 90Degree grid 0.2 track 0.2, remove dead copper, pour order 91): 20 vertices, not listed, extent 27.5,83 43.5,87.95
AGND on Top Layer "Bottom Layer-No Net 1" (hatched 90Degree grid 0.2 track 0.2, remove dead copper, pour order 97): 42 vertices, not listed, extent 27.59,87.567 55.55,110.43
GND on Top Layer "Bottom Layer-No Net 1" (hatched 90Degree grid 0.2 track 0.2, remove dead copper, pour order 153): 78.5,103.27 77.62,104.15 77.62,107.43 78.08,107.89 78.62,107.89 82.22,104.29 82.22,103.97 81.52,103.27
AGND on Top Layer "Bottom Layer-No Net" (solid, remove dead copper, pour order 110): 24 vertices, not listed, extent 86,42.5 99.644,50.59

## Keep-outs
Keep-Out Layer:
  circle w0.1: c3.5,3.5 r1.75
  circle w0.1: c146.5,146.5 r1.75
  circle w0.1: c146.5,3.5 r1.75
  circle w0.1: c3.5,146.5 r1.75
  lines w0.1: 0,0 150,0 150,150 0,150 0,0

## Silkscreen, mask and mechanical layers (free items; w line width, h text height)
Top Overlay:
  drawing of 1493 lines, arcs and shapes, not listed
  text "RESET" at 97.416,112 h3
  text "DGND" at 114.22,111.01 h1.5
  text "DGND" at 123.093,111.01 h1.5
  text "DGND" at 131.967,111.01 h1.5
  text "DGND" at 140.84,111.01 h1.5
  text "GND" at 73.38,109.75 h1.2 r45
  text "VCC" at 76.08,109.75 h1.2 r45
  text "UART_TXD" at 68.28,109.65 h1.2 r45
  text "UART_RXD" at 70.88,109.65 h1.2 r45
  text "XRSTN" at 56.86,109.15 h1.2 r45
  text "TRSTN" at 59.5,109.15 h1.2 r45
  text "IO39" at 48.66,109.1 h1.2 r45
  text "IO38" at 51.36,109.1 h1.2 r45
  text "IO40" at 114.513,107.07 h2
  text "TRSTn" at 122.89,107.07 h1.5
  text "IO30" at 132.26,107.07 h2
  text "IO31" at 141.133,107.07 h2
  text "ADC0" at 37.4,105.6 h2
  text "DVDD" at 114.22,104.19 h1.5
  text "DVDD" at 123.093,104.19 h1.5
  text "DVDD" at 131.967,104.19 h1.5
  text "DVDD" at 140.84,104.19 h1.5
  text "ADC1" at 37.4,103.06 h2
  text "DVDD_3V3" at 57.34,102.27 h1.2
  text "IO40" at 48,101.116 h1.2 r45
  text "IO35" at 50.4,101.11 h1.2 r45
  text "IO34" at 52.4,101.1 h1.2 r45
  text "GND" at 55.2,101.049 h1.2 r45
  text "GND" at 61.06,100.57 h2
  text "ADC2" at 37.4,100.52 h2
  text "VCAP12" at 98.67,98.408 h2
  text "ADC3" at 37.4,97.98 h2
  text "ADC4" at 37.3,95.6 h2
  text "IO40" at 48.41,94.23 h1.5 r270
  text "XRSTN" at 50.98,94.23 h1.5 r270
  text "TRSTN" at 53.49,94.23 h1.5 r270
  text "IO39" at 55.86,94.23 h1.5 r270
  text "IO38" at 58.61,94.23 h1.5 r270
  text "IO37" at 74.552,94.03 h1.5 r270
  text "IO36" at 75.833,94.03 h1.5 r270
  text "IO35" at 77.114,94.03 h1.5 r270
  text "IO34" at 78.396,94.03 h1.5 r270
  text "IO32" at 80.958,94.03 h1.5 r270
  text "IO31" at 82.239,94.03 h1.5 r270
  text "IO30" at 83.52,94.03 h1.5 r270
  text "ADC5" at 37.4,92.9 h2
  text "VCAP12" at 140.8,92.8 h1.5
  text "DVDD_3V3" at 107.72,90.42 h1.5
  text "ADC14" at 37.4,90.36 h2
  text "VDD_1V3" at 140.8,90.2 h1.5
  text "ADC15" at 37.4,87.82 h2
  text "DVDD_3V3" at 95.8,86.8 h3
  text "VDD_3V3" at 111.9,85.4 h1.5
  text "AVDD_3V3" at 42.78,84.98 h1.5 r270
  text "AVDD" at 50.28,82.83 h2 r270
  text "GND" at 93.1,77.2 h3
  text "ADC8" at 36.4,77.04 h1.5
  text "ADC13" at 36.4,74.5 h1.5
  text "VDD_5V" at 140.6,74.5 h1.5
  text "ADC6" at 36.4,73.2 h1.5
  text "ADC7" at 36.4,72 h1.5
  text "BUCK_OUT5V" at 140.7,72 h1.5
  text "VDD_3V3" at 114.5,67.1 h3 r90
  text "AGND" at 92.35,65.17 h3
  text "AVDD_3V3" at 76.33,56.37 h2
  text "VDAC_BUF1" at 17.8,42.767 h2
  text "VDAC_BUF0" at 68.7,37.8 h2
  text "VREF_1V2" at 39.6,37.7 h2
  text "ATEST" at 56.2,37.7 h2
  text "VREF_3V3" at 84.3,37.7 h2
  text "VREF_3V3" at 97,37.7 h2
  text "SPD1178.ENGR.190802" at 46.7,33.167 h4
  text "SPD1178.ENGR.190802" at 41.109,-17.68 h4
  text "技术要求：" at 40.729,-21.91 h3
  text "1、PCB板材质Tg：135度；" at 54.552,-22.31 h3
  text "2、上、下层丝印为白色，阻焊为绿色；" at 54.549,-26.219 h3
  text "3、所用板材必须阻燃,成品板CTI大于等于400，吸水率小于5%；；" at 54.552,-29.727 h3
  text "4、符合ROHS/UL/CQC要求" at 54.552,-33.452 h3
  text "5、单板71*63mm，板厚：1.6mm，铜厚:35um；" at 54.552,-37.06 h3
  text "6、过孔是否绿油根据过孔的设置来；" at 54.659,-40.63 h3
  text "7、芯片的引脚中间必须喷绿油，特别是CHIP." at 54.769,-44.25 h3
